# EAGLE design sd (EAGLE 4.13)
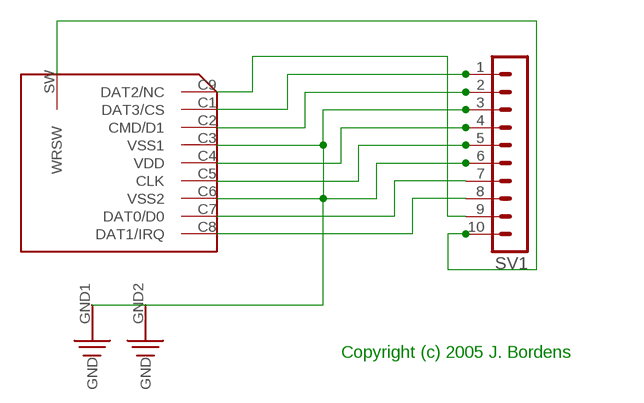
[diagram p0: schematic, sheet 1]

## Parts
SV1  MA10-1  [MA10-1]
U$1  CCM05  [CCM05]

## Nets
N$1: SV1.1 U$1.C1(SDCARD:DAT3/CS)
N$2: SV1.2 U$1.C2(SDCARD:CMD/D1)
N$3: SV1.3 SV1.6 U$1.C3(SDCARD:VSS1) U$1.C6(SDCARD:VSS2) U$1.GND1(GND1:GND) U$1.GND2(GND2:GND)
N$4: SV1.4 U$1.C4(SDCARD:VDD)
N$5: SV1.5 U$1.C5(SDCARD:CLK)
N$7: SV1.7 U$1.C7(SDCARD:DAT0/D0)
N$8: SV1.8 U$1.C8(SDCARD:DAT1/IRQ)
N$9: SV1.9 U$1.C9(SDCARD:DAT2/NC)
N$10: SV1.10 U$1.SW(SDCARD:WRSW)

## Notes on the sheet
- Copyright (c) 2005 J. Bordens

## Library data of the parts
SV1 = con-lstb:MA10-1: PIN HEADER
U$1 = sd:CCM05

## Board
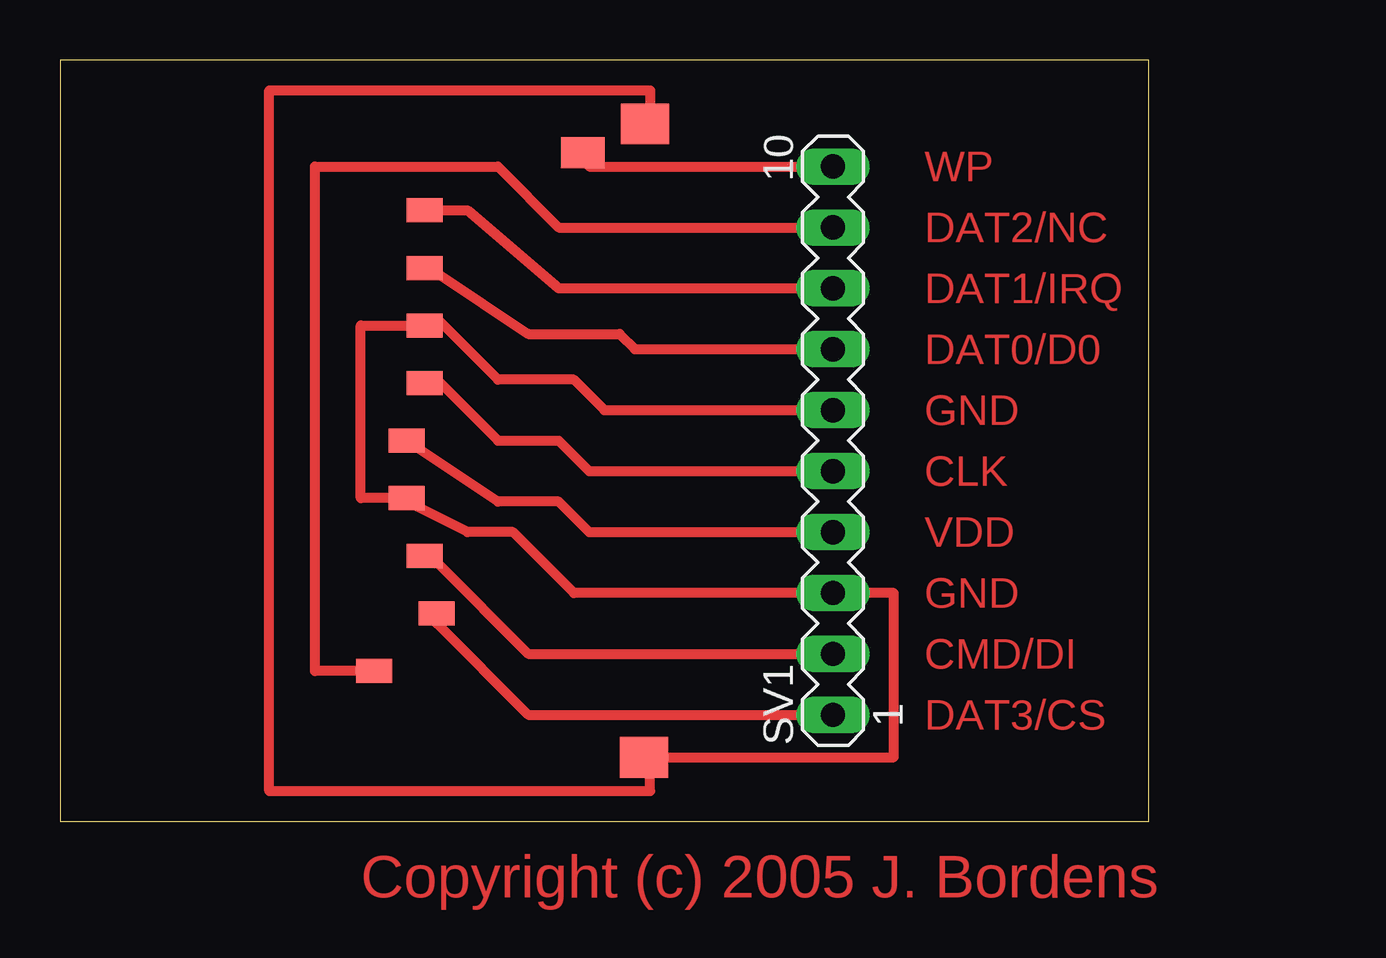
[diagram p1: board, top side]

Size 45.39 x 31.74 mm. Coordinates in mm from the lower left corner, seen from the top.
Outline: 0,0 45.39,0 45.39,31.74 0,31.74 0,0
Copper layers (1*16): Top 0.035mm / dielectric 1.5mm / Bottom 0.035mm
Design rules "default": minimum track width 10mil, minimum drill 24mil, track to track 8mil, track to pad 8mil, pad to pad 8mil, via to via 8mil, smd to smd 8mil, copper to edge 40mil, drill to drill 8mil, minimum pad ring 10mil, minimum via ring 8mil, stop-mask expansion 4mil, vias tented up to drill 0mil, thermal gap 10mil

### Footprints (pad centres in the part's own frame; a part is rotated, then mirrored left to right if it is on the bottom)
MA10-1 = drill 1.016 long: 1 -11.43,0; 2 -8.89,0; 3 -6.35,0; 4 -3.81,0; 5 -1.27,0; 6 1.27,0; 7 3.81,0; 8 6.35,0; 9 8.89,0; 10 11.43,0
CCM05@1 = smd 1.5 x 1: C1 1.25,-7.2; C2 0.75,-4.8; C3 0,-2.4; C4 0,0; C5 0.75,2.4; C6 0.75,4.8; C7 0.75,7.2; C8 0.75,9.6; C9 -1.35,-9.6 | smd 2 x 1.7: GND1 9.95,13.2; GND2 9.9,-13.2 | smd 1.8 x 1.3: SW 7.35,12

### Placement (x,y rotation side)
SV1  32.22,15.87 90 top
U$1  CCM05  [CCM05@1]  14.44,15.87 0 top

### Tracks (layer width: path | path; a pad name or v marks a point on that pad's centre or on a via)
N$1
  Top 0.254: U$1.C1 15.71,8.25
  Top 0.406: 15.71,8.25 19.52,4.44 SV1.1
N$2
  Top 0.254: U$1.C2 15.71,10.79
  Top 0.406: 15.71,10.79 19.52,6.98 SV1.2
N$3
  Top 0.254: 14.44,13.33 U$1.C3 | U$1.C6 15.71,20.95
  Top 0.406: 14.44,13.33 16.98,12.06 18.88,12.06 21.42,9.52 30.95,9.52 SV1.3 34.76,9.52 34.76,2.67 U$1.GND2 24.6,2.67 24.6,1.27 8.73,1.27 8.73,30.47 24.6,30.47 24.6,29.07 U$1.GND1 | 15.71,20.95 18.25,18.41 21.42,18.41 22.7,17.14 SV1.6 | U$1.C3 12.54,13.47 12.54,20.67 U$1.C6
N$4
  Top 0.406: U$1.C4 18.25,13.33 20.79,13.33 22.06,12.06 SV1.4
N$5
  Top 0.254: U$1.C5 15.71,18.41
  Top 0.406: 15.71,18.41 18.25,15.87 20.79,15.87 22.06,14.6 SV1.5
N$7
  Top 0.254: U$1.C7 15.71,22.86
  Top 0.406: 15.71,22.86 19.52,20.31 23.33,20.31 23.96,19.68 SV1.7
N$8
  Top 0.406: U$1.C8 16.98,25.47 20.79,22.22 SV1.8
N$9
  Top 0.406: U$1.C9 10.63,6.27 10.63,27.3 18.25,27.3 20.79,24.76 SV1.9
N$10
  Top 0.254: U$1.SW 22.06,27.3
  Top 0.406: 22.06,27.3 SV1.10

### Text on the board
Top: WP | DAT2/NC | DAT1/IRQ | DAT0/D0 | GND | CLK | VDD | GND | CMD/DI | DAT3/CS | Copyright (c) 2005 J. Bordens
